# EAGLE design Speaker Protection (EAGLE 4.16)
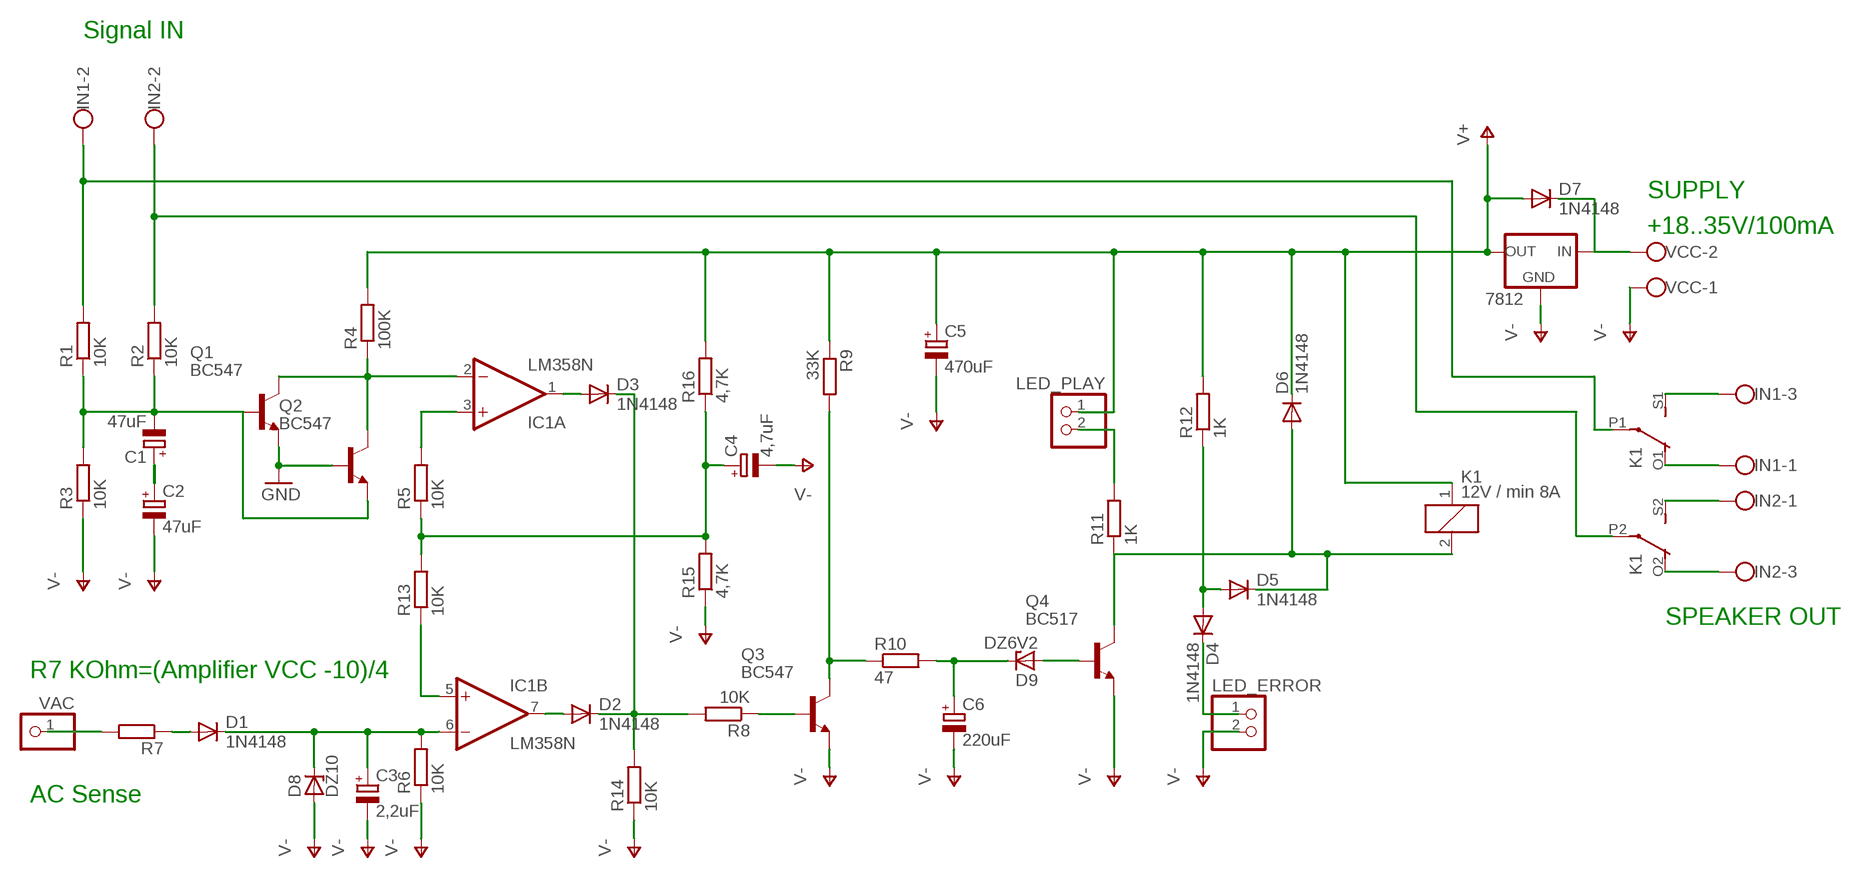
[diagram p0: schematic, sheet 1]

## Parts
7812  78XXS  [78XXS]
C1  47uF  CPOL-EUE2-5  [E2-5]
C2  47uF  CPOL-EUE2-5  [E2-5]
C3  2,2uF  CPOL-EUE2-5  [E2-5]
C4  4,7uF  CPOL-EUE2-5  [E2-5]
C5  470uF  CPOL-EUE3.5-8  [E3,5-8]
C6  220uF  CPOL-EUE2.5-6  [E2,5-6]
D1  1N4148  BAS15  [DO34-7]
D2  1N4148  BAS15  [DO34-7]
D3  1N4148  BAS15  [DO34-7]
D4  1N4148  BAS15  [DO34-7]
D5  1N4148  BAS15  [DO34-7]
D6  1N4148  BAS15  [DO34-7]
D7  1N4148  BAS15  [DO34-7]
D8  DZ10  ZENER-DIODEDO34-7  [DO34Z7]
D9  DZ6V2  ZENER-DIODEDO34-7  [DO34Z7]
IC1  LM358N  [DIL08]
IN1  W237-3E  [W237-3E]
IN2  W237-3E  [W237-3E]
K1  12V / min 8A  4052  [F4052]
LED_ERROR  PINHD-1X2  [1X02]
LED_PLAY  PINHD-1X2  [1X02]
Q1  BC547  BC338-25  [TO92-EBC]
Q2  BC547  BC338-25  [TO92-EBC]
Q3  BC547  BC338-25  [TO92-EBC]
Q4  BC517  BC338-25  [TO92-EBC]
R1  10K  R-EU_0207/10  [0207/10]
R2  10K  R-EU_0207/10  [0207/10]
R3  10K  R-EU_0204/5  [0204/5]
R4  100K  R-EU_0207/10  [0207/10]
R5  10K  R-EU_0204/5  [0204/5]
R6  10K  R-EU_0204/7  [0204/7]
R7  R-EU_0204/5  [0204/5]
R8  10K  R-EU_0204/5  [0204/5]
R9  33K  R-EU_0204/5  [0204/5]
R10  47  R-EU_0204/5  [0204/5]
R11  1K  R-EU_0204/7  [0204/7]
R12  1K  R-EU_0204/5  [0204/5]
R13  10K  R-EU_0204/7  [0204/7]
R14  10K  R-EU_0204/5  [0204/5]
R15  4,7K  R-EU_0204/5  [0204/5]
R16  4,7K  R-EU_0204/5  [0204/5]
VAC  PINHD-1X1  [1X01]
VCC  W237-02P  [W237-132]

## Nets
GND: Q1.E Q2.B
N$1: C1.- Q1.B Q2.E R1.1 R2.1 R3.2
N$2: C1.+ C2.+
N$3: IN1.3 K1.S1(2:S)
N$4: IC1.3(A:+IN) R5.2
N$5: IC1.2(A:-IN) Q1.C Q2.C R4.1
N$6: IC1.5(B:+IN) R13.1
N$7: C4.+ R5.1 R13.2 R15.2 R16.1
N$8: D1.A R7.1
N$9: C3.+ D1.C D8.C IC1.6(B:-IN) R6.2
N$10: D3.A IC1.1(A:OUT)
N$11: D2.A IC1.7(B:OUT)
N$12: D2.C D3.C R8.2 R14.2
N$13: IN1.1 K1.O1(2:O)
N$14: R7.2 VAC.1
N$15: Q3.B R8.1
N$16: Q3.C R9.2 R10.1
N$17: C6.+ D9.C R10.2
N$18: D9.A Q4.B
N$20: LED_PLAY.2 R11.2
N$21: D4.A D5.A R12.1
N$22: D4.C LED_ERROR.1
N$23: D5.C D6.A K1.2 Q4.C R11.1
N$24: 7812.IN D7.C VCC.2
N$25: IN2.3 K1.O2(3:O)
N$26: IN2.1 K1.S2(3:S)
N$29: IN2.2 K1.P2(3:P) R2.2
N$30: IN1.2 K1.P1(2:P) R1.2
V+: 7812.OUT C5.+ D6.C D7.A K1.1 LED_PLAY.1 R4.2 R9.1 R12.2 R16.2
V-: 7812.GND C2.- C3.- C4.- C5.- C6.- D8.A LED_ERROR.2 Q3.E Q4.E R3.1 R6.1 R14.1 R15.1 VCC.1

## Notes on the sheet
- Signal IN
- SUPPLY
- +18..35V/100mA
- SPEAKER OUT
- R7 KOhm=(Amplifier VCC -10)/4
- AC Sense

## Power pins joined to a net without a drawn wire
V+: IC1.8(P:V+)
V-: IC1.4(P:V-)

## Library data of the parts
7812 = v-reg:78XXS: VOLTAGE REGULATOR
C1-C6 = rcl:CPOL-EU: POLARIZED CAPACITOR, European symbol
D1-D7 = diode:BAS15: DIODE
D8 D9 = diode:ZENER-DIODE: Z-Diode
IC1 = linear:LM358: OP AMP
IN1 IN2 = con-wago-508:W237-3E: WAGO SREW CLAMP
K1 = relay:4052: RELAY 2 x switch, Finder
LED_ERROR LED_PLAY = pinhead:PINHD-1X2: PIN HEADER
Q1-Q4 = transistor-npn:BC338*: NPN Transistor
R1-R16 = rcl:R-EU_: RESISTOR, European symbol
VAC = pinhead:PINHD-1X1: PIN HEADER
VCC = con-wago-508:W237-02P: WAGO SREW CLAMP

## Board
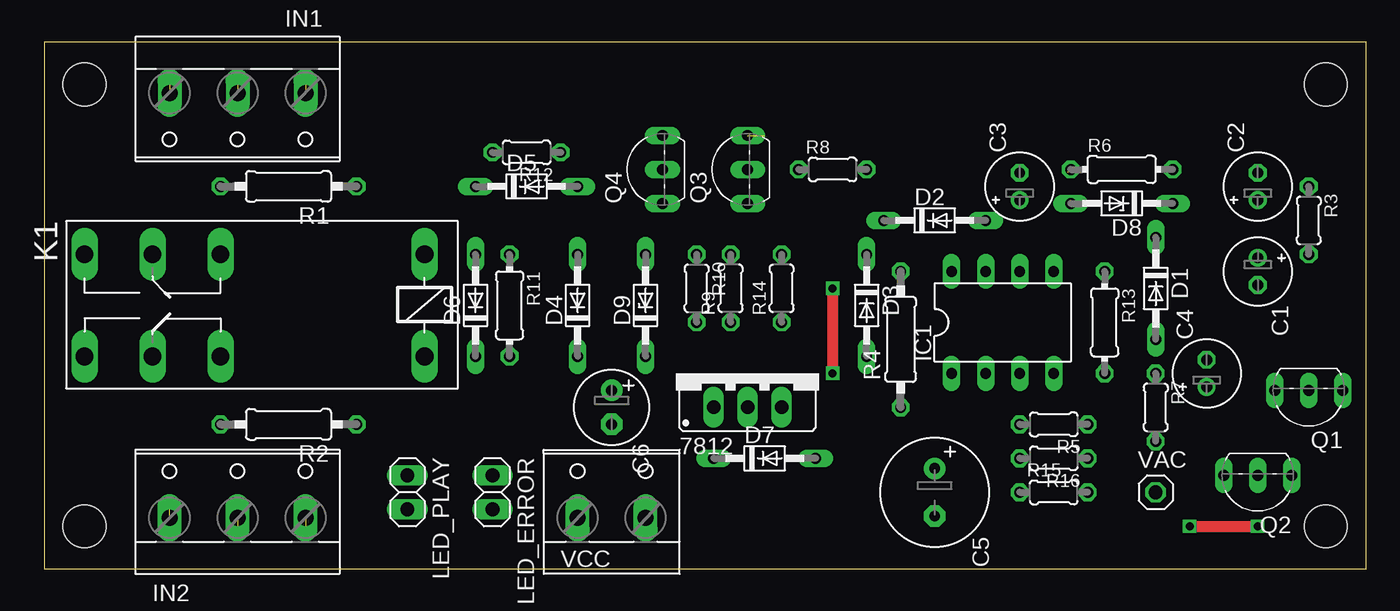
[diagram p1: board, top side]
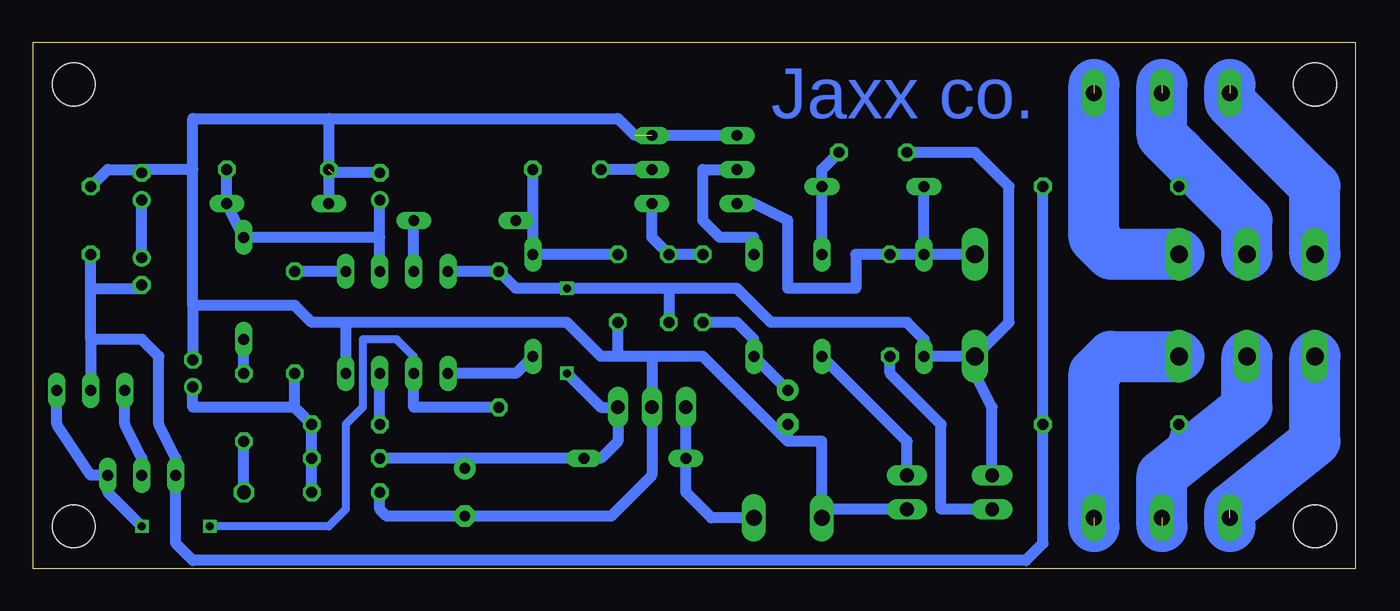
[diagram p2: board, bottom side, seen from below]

Size 98.73 x 39.36 mm. Coordinates in mm from the lower left corner, seen from the top.
Outline: 0,0 98.73,0 98.73,39.36 0,39.36 0,0
Copper layers (1*16): Top 0.035mm / dielectric 1.5mm / Bottom 0.035mm
Design rules "default": minimum track width 10mil, minimum drill 24mil, track to track 8mil, track to pad 8mil, pad to pad 8mil, via to via 8mil, smd to smd 8mil, copper to edge 40mil, drill to drill 8mil, minimum pad ring 10mil, minimum via ring 8mil, stop-mask expansion 4mil, vias tented up to drill 0mil, thermal gap 10mil
Holes 3.2 mm at 95.72,36.19 95.72,3.17 3.01,3.17 3.01,36.19

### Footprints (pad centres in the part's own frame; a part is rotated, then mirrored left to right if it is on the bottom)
78XXS = drill 1.016 long: GND 0,-2.54; IN -2.54,-2.54; OUT 2.54,-2.54
E2-5 = drill 0.813 pad 1.27 round: + -1.016,0 | drill 0.813 pad 1.27 octagon: - 1.016,0
E3,5-8 = drill 0.813 pad 1.6 round: + -1.778,0 | drill 0.813 pad 1.6 octagon: - 1.778,0
E2,5-6 = drill 0.813 pad 1.6 round: + -1.27,0 | drill 0.813 pad 1.6 octagon: - 1.27,0
DO34-7 = drill 0.813 long: A 3.81,0; C -3.81,0
DO34Z7 = drill 0.813 long: A 3.81,0; C -3.81,0
DIL08 = drill 0.813 long: 1 -3.81,-3.81; 2 -1.27,-3.81; 3 1.27,-3.81; 4 3.81,-3.81; 5 3.81,3.81; 6 1.27,3.81; 7 -1.27,3.81; 8 -3.81,3.81
W237-3E = drill 1.194 long: 1 -5.08,-0.635; 2 0,-0.635; 3 5.08,-0.635
F4052 = drill 1.321 long: 1 -3.81,3.81; 2 -3.81,-3.81; O1 11.43,-3.81; O2 11.43,3.81; P1 16.51,-3.81; P2 16.51,3.81; S1 21.59,-3.81; S2 21.59,3.81
1X02 = drill 1.016 long: 1 -1.27,0; 2 1.27,0
TO92-EBC = drill 0.813 long: B 0,-1.27; C -2.54,-1.27; E 2.54,-1.27
0207/10 = drill 0.813 octagon: 1 -5.08,0; 2 5.08,0
0204/5 = drill 0.813 octagon: 1 -2.54,0; 2 2.54,0
0204/7 = drill 0.813 octagon: 1 -3.81,0; 2 3.81,0
1X01 = drill 1.016 octagon: 1 0,0
W237-132 = drill 1.194 long: 1 -2.54,-0.635; 2 2.54,-0.635

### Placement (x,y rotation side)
7812  52.54,14.6 0 top
C1  90.64,22.22 270 top
C2  90.64,28.57 90 top
C3  72.86,28.57 90 top
C4  86.83,14.6 90 top
C5  66.51,5.71 270 top
C6  42.38,12.06 270 top
D1  83.02,20.95 270 top
D2  66.51,26.03 0 top
D3  61.43,19.68 270 top
D4  39.84,19.68 90 top
D5  36.03,28.57 0 top
D6  32.22,19.68 90 top
D7  53.81,8.25 0 top
D8  80.48,27.3 180 top
D9  44.92,19.68 90 top
IC1  71.59,18.41 0 top
IN1  14.44,34.92 180 top
IN2  14.44,4.44 0 top
K1  24.6,19.68 180 top
LED_ERROR  33.49,5.71 270 top
LED_PLAY  27.14,5.71 270 top
Q1  94.45,12.06 180 top
Q2  90.64,5.71 180 top
Q3  51.27,29.84 90 top
Q4  44.92,29.84 90 top
R1  18.25,28.57 180 top
R2  18.25,10.79 180 top
R3  94.45,26.03 270 top
R4  63.97,17.14 90 top
R5  75.4,10.79 180 top
R6  80.48,29.84 0 top
R7  83.02,12.06 270 top
R8  58.89,29.84 0 top
R9  51.27,20.95 90 top
R10  48.73,20.95 270 top
R11  34.76,19.68 270 top
R12  36.03,31.11 180 top
R13  79.21,18.41 270 top
R14  55.08,20.95 90 top
R15  75.4,5.71 0 top
R16  75.4,8.25 180 top
VAC  83.02,5.71 0 top
VCC  42.38,4.44 0 top

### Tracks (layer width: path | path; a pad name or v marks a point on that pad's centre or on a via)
GND
  Bottom 0.813: Q1.E 91.91,10.79 90.64,8.25 Q2.B
N$1
  Bottom 0.813: R1.1 R2.1 23.33,1.9 24.6,0.63 86.83,0.63 88.1,1.9 Q2.E 88.1,8.25 89.37,10.79 89.37,15.87 90.64,17.14 94.45,17.14 | 94.45,17.14 Q1.B | 94.45,17.14 94.45,20.95 | 94.45,20.95 R3.2 | C1.- 90.64,20.95 94.45,20.95
N$2
  Bottom 0.813: C1.+ C2.+
N$3  (1 unrouted)
  Bottom 3.81: K1.S1 3.01,28.57 9.36,34.92 9.36,36.19
N$4
  Bottom 0.813: R5.2 IC1.3
N$5  (via drill 0.6)
  Top 0.813: v85.56,3.17 v90.64,3.17
  Bottom 0.61: IC1.2 70.32,15.87 71.59,17.14 74.13,17.14 74.13,12.06 75.4,10.79 75.4,4.44 76.67,3.17 v85.56,3.17
  Bottom 0.813: R4.1 70.32,12.06 IC1.2 | Q1.C 96.99,10.79 94.45,6.98 Q2.C 93.18,5.71 v90.64,3.17
N$6
  Bottom 0.813: IC1.5 R13.1
N$7
  Bottom 0.813: 79.21,12.06 R13.2 | R15.2 R16.1 R5.1 79.21,12.06 | 79.21,12.06 86.83,12.06 C4.+
N$8
  Bottom 0.813: R7.1 D1.A
N$9
  Bottom 0.813: IC1.6 72.86,24.76 | 72.86,24.76 C3.+ | R6.2 D8.C D1.C 72.86,24.76
N$10
  Bottom 0.813: IC1.1 62.7,14.6 D3.A
N$11
  Bottom 0.813: IC1.7 D2.A
N$12
  Bottom 0.813: 61.43,26.03 R8.2 | 61.43,26.03 D2.C | 61.43,26.03 D3.C R14.2
N$13  (1 unrouted)
  Bottom 3.81: K1.O1 18.25,23.49 19.52,24.76 19.52,36.19
N$14
  Bottom 0.813: VAC.1 R7.2
N$15
  Bottom 0.813: Q3.B R8.1
N$16
  Bottom 0.813: Q3.C 52.54,24.76 R9.2 R10.1
N$17
  Bottom 0.813: R10.2 46.19,18.41 44.92,17.14 D9.C C6.+
N$18
  Bottom 0.813: Q4.B 48.73,29.84 48.73,26.03 47.46,24.76 44.92,24.76 D9.A
N$20
  Bottom 0.813: R11.2 34.76,14.6 30.95,10.79 30.95,4.44 LED_PLAY.2
N$21
  Bottom 0.813: R12.1 39.84,29.84 D5.A D4.A
N$22
  Bottom 0.813: LED_ERROR.1 33.49,9.52 D4.C
N$23
  Bottom 0.813: K1.2 D6.A | D6.A R11.1 37.3,23.49 37.3,20.95 42.38,20.95 42.38,26.03 44.92,27.3 Q4.C | D6.A D5.C
N$24
  Bottom 0.813: 7812.IN D7.C 50,5.71 48.09,3.8 VCC.2
N$25  (1 unrouted)
  Bottom 3.81: K1.O2 18.25,15.87 19.52,14.6 19.52,3.17
N$26  (1 unrouted)
  Bottom 3.81: K1.S2 3.01,9.52 9.36,4.44 9.36,3.17
N$29  (1 unrouted)
  Bottom 0.813: 14.44,6.98 R2.2
  Bottom 3.81: K1.P2 8.09,12.06 14.44,6.98 14.44,3.17
N$30  (1 unrouted)
  Bottom 0.813: 13.17,31.11 R1.2
  Bottom 3.81: K1.P1 8.09,26.03 13.17,31.11 14.44,32.38 14.44,36.19
V+  (via drill 0.6)
  Top 0.813: v58.89,20.95 v58.89,14.6
  Bottom 0.813: K1.1 D6.C 32.22,17.14 33.49,18.41 43.65,18.41 46.19,20.95 51.27,20.95 | R12.2 28.41,31.11 25.87,28.57 25.87,18.41 K1.1 | IC1.8 R4.2 62.7,20.95 v58.89,20.95 51.27,20.95 | LED_PLAY.1 27.14,12.06 28.41,14.6 K1.1 | 56.35,8.25 D7.A | 56.35,8.25 55.08,9.52 7812.OUT 56.35,12.06 v58.89,14.6 | 66.51,8.25 R16.2 | 66.51,8.25 C5.+ | 56.35,8.25 66.51,8.25 | 51.27,20.95 R9.1
V-  (2 unrouted)
  Bottom 0.813: 75.4,18.41 IC1.4 | 75.4,18.41 58.89,18.41 56.35,15.87 55.08,15.87 | C3.- 76.42,29.59 | 53.81,32.38 55.08,33.65 76.67,33.65 | 76.67,33.65 86.83,33.65 86.83,29.84 | 86.83,19.68 86.83,29.84 | Q4.E Q3.E | 75.4,18.41 77.94,18.41 79.21,19.68 86.83,19.68 | 52.54,15.87 7812.GND 52.54,6.98 55.59,3.93 C5.- 72.35,3.93 72.86,4.44 R15.1 | 52.54,15.87 55.08,15.87 | 55.08,15.87 R14.1 | 39.84,4.44 VCC.1 | 39.84,4.44 39.84,9.52 42.38,9.52 | 42.38,9.52 48.73,15.87 52.54,15.87 | LED_ERROR.2 39.84,4.44 | 76.67,33.65 R6.1 D8.A | 86.83,19.68 C4.- | 42.38,9.52 C6.- | 86.83,29.84 90.64,29.84 | R3.1 93.18,29.84 90.64,29.84 | 90.64,29.84 C2.-

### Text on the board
Bottom: Jaxx co.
